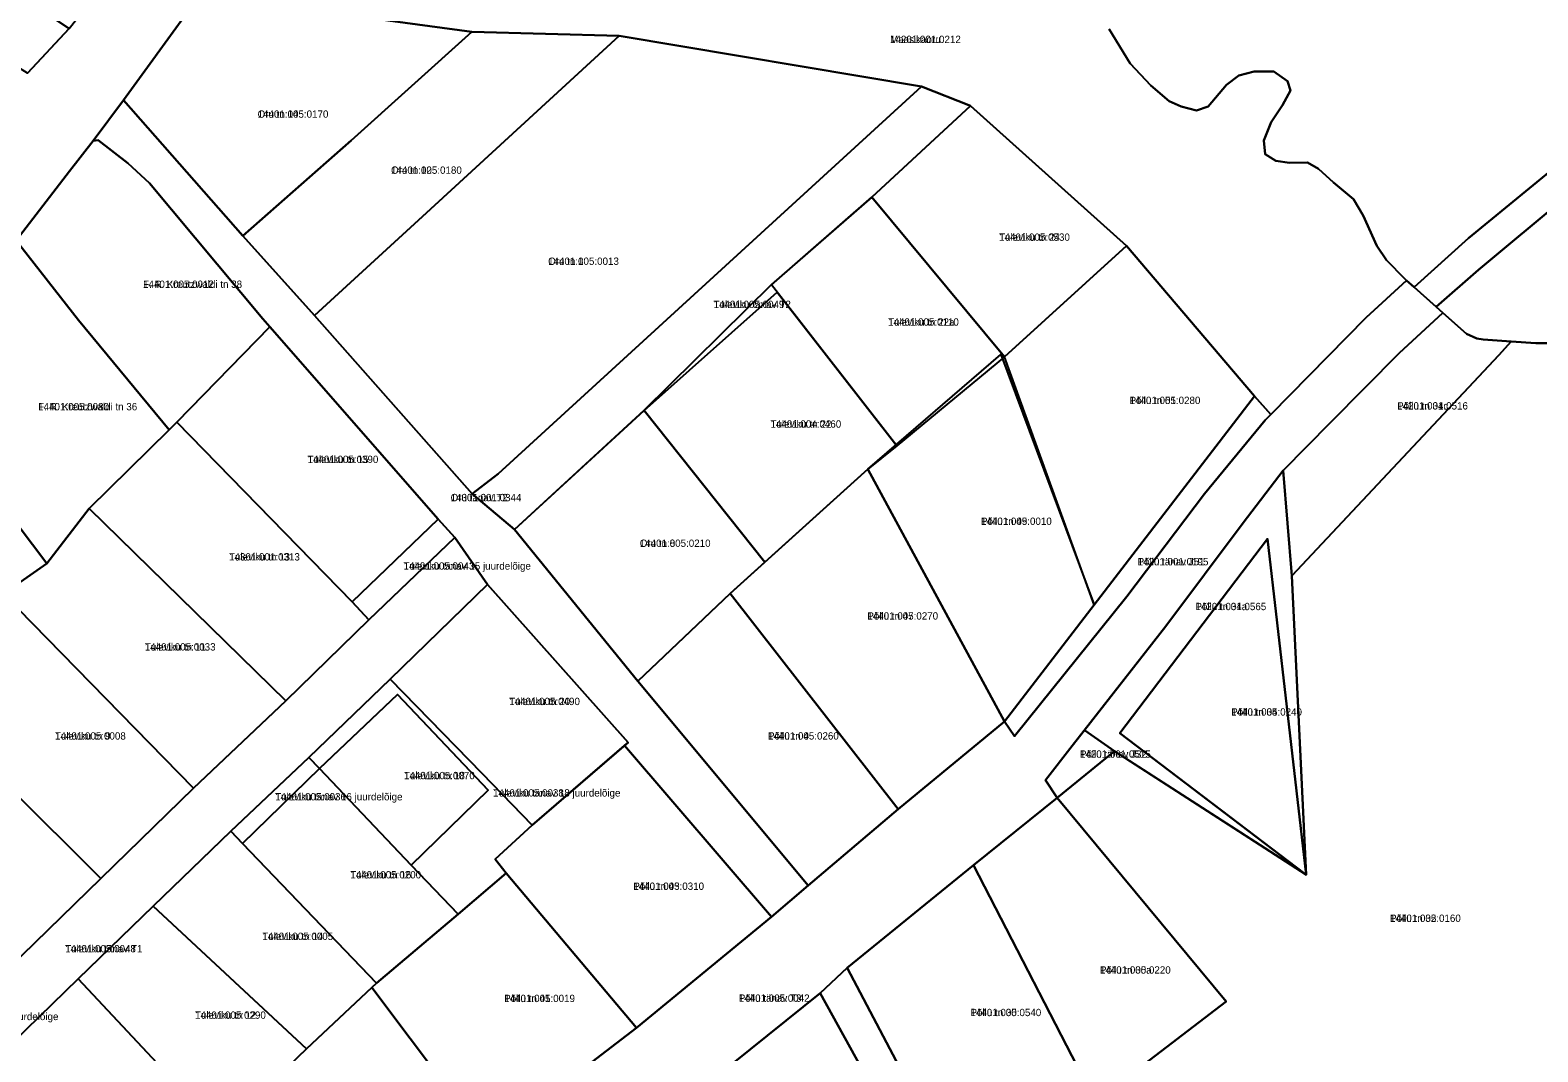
# Model space of a CAD drawing. Extents: x 640657 to 665127, y 6395726 to 6426831.
# Drawn here: x 650809.6 to 651118.5, y 6412851.6 to 6413060.8 of the extents above; entities that cross this region are included whole.
import ezdxf

# ---------------------------------------------------------------- set-up
doc = ezdxf.new("R2010")
doc.units = 0
for name, color, linetype in [('L_AADRESS', 7, 'Continuous'), ('PIIR', 7, 'Continuous'), ('TUNNUS', 7, 'Continuous')]:
    doc.layers.add(name, color=color, linetype=linetype)

msp = doc.modelspace()

# ---------------------------------------------------------------- linework, layer by layer
at = {"layer": 'PIIR'}
for points in [[(650639.81, 6413174.35), (650661.38, 6413159.66), (650687.87, 6413141.56), (650726.69, 6413115.56), (650728.32, 6413120.2), (650817.6, 6413061.15), (650809.09, 6413051.96), (650774.49, 6413073.67), (650757.49, 6413085.02), (650736.91, 6413098.43), (650728.56, 6413104.06), (650707.39, 6413117.67), (650694.6, 6413126.1), (650690.86, 6413128.47), (650674.2, 6413139.68), (650668.91, 6413143.29), (650635.45, 6413166.68)], [(650828.73, 6413046.43), (650842.18, 6413064.93), (650852, 6413067.01), (650900.11, 6413060.4), (650875.35, 6413038.19), (650853.19, 6413018.67)], [(650889.96, 6413022.62), (650867.85, 6413002.33), (650853.19, 6413018.67), (650875.35, 6413038.19), (650900.11, 6413060.4), (650930.28, 6413059.63)], [(650930.28, 6413059.63), (650992.19, 6413049.22), (650905.51, 6412969.94), (650900.17, 6412965.79), (650867.85, 6413002.33), (650889.96, 6413022.62)], [(650900.17, 6412965.79), (650905.51, 6412969.94), (650992.19, 6413049.22), (651002.25, 6413045.27), (650982.01, 6413026.6), (650961.49, 6413008.66), (650935.36, 6412982.86), (650908.86, 6412958.51)], [(650822.51, 6413038.14), (650828.73, 6413046.43), (650853.19, 6413018.67), (650867.85, 6413002.33), (650900.17, 6412965.79), (650908.86, 6412958.51), (650934.1, 6412927.48), (650968.99, 6412885.61), (650961.49, 6412879.2), (650931.36, 6412914.3), (650932.1, 6412914.93), (650903.31, 6412947.28), (650896.59, 6412956.91), (650893.22, 6412960.61), (650858.72, 6412999.99), (650857.25, 6413001.69), (650834.03, 6413029.42), (650829.61, 6413033.56), (650823.57, 6413038.25)], [(650982.01, 6413026.6), (651002.25, 6413045.27), (651034.21, 6413016.63), (651009.24, 6412993.91)], [(650806.76, 6413017.69), (650817.7, 6413031.91), (650822.51, 6413038.14), (650823.57, 6413038.25), (650829.61, 6413033.56), (650834.03, 6413029.42), (650857.25, 6413001.69), (650858.72, 6412999.99), (650839.66, 6412980.52), (650838.08, 6412978.9), (650819.54, 6413001.38)], [(650987.17, 6412975.63), (650961.49, 6413008.65), (650982.01, 6413026.6), (651009.24, 6412993.91)], [(650806.76, 6413017.69), (650819.54, 6413001.38), (650838.08, 6412978.9), (650821.71, 6412962.79), (650813.02, 6412951.56), (650784.43, 6412989.36)], [(651009.24, 6412993.91), (651034.21, 6413016.63), (651060.45, 6412985.8), (651027.56, 6412943.08)], [(650960.14, 6412951.85), (650935.37, 6412982.87), (650962.68, 6413007.13), (650987.17, 6412975.63), (650981.24, 6412970.86)], [(651099, 6413002.9), (651103.86, 6412998.61), (651105.99, 6412997.64), (651107.31, 6412997.44), (651113.02, 6412997.03), (651110.49, 6412994.23), (651068.11, 6412949.05), (651066.3, 6412970.6), (651076, 6412980.4), (651090.1, 6412994.6)], [(650875.6, 6412943.69), (650839.66, 6412980.52), (650858.72, 6412999.99), (650893.22, 6412960.61)], [(651027.56, 6412943.08), (651009.2, 6412919.23), (650981.24, 6412970.86), (651008.5, 6412994.35)], [(650760.68, 6412958.63), (650784.43, 6412989.36), (650813.02, 6412951.56), (650804.18, 6412945.36), (650788.46, 6412927.08)], [(651009.2, 6412919.23), (651027.56, 6412943.08), (651060.45, 6412985.8), (651063.77, 6412982.09), (651062.6, 6412980.9), (651050.2, 6412965.8), (651034.3, 6412944.8), (651011.3, 6412916.2)], [(650934.1, 6412927.48), (650908.86, 6412958.51), (650935.37, 6412982.87), (650960.14, 6412951.85), (650953.05, 6412945.43)], [(650862, 6412923.4), (650821.71, 6412962.79), (650838.08, 6412978.9), (650839.66, 6412980.52), (650875.6, 6412943.69), (650879, 6412940)], [(650981.24, 6412970.86), (651009.2, 6412919.23), (650987.44, 6412901.27), (650953.05, 6412945.43)], [(651071.04, 6412887.8), (651063.12, 6412956.6), (651032.82, 6412916.84), (651070.71, 6412888.05), (651031.76, 6412913.14), (651025.64, 6412917.44), (651042.3, 6412938.7), (651058.1, 6412959.9), (651066.3, 6412970.6), (651068.11, 6412949.05)], [(650843.09, 6412905.57), (650804.18, 6412945.36), (650813.02, 6412951.56), (650821.71, 6412962.79), (650862, 6412923.4)], [(650875.6, 6412943.69), (650893.22, 6412960.61), (650896.59, 6412956.91), (650879, 6412940)], [(650727.79, 6412797.05), (650764.12, 6412829.22), (650781.76, 6412846.39), (650802.47, 6412866.04), (650824.08, 6412887.05), (650843.09, 6412905.57), (650862, 6412923.4), (650879, 6412940), (650896.59, 6412956.91), (650903.31, 6412947.28), (650883.38, 6412927.9), (650866.67, 6412911.86), (650850.73, 6412896.72), (650834.83, 6412881.39), (650819.43, 6412866.53), (650803.47, 6412850.91), (650787.59, 6412835.68), (650771.66, 6412820.55), (650754.96, 6412806.32), (650734.58, 6412786.93)], [(651032.82, 6412916.84), (651063.12, 6412956.6), (651071.04, 6412887.8)], [(650786.31, 6412924.61), (650788.46, 6412927.08), (650804.18, 6412945.36), (650843.09, 6412905.57), (650824.08, 6412887.05)], [(650903.31, 6412947.28), (650932.1, 6412914.93), (650912.45, 6412897.98), (650902.19, 6412908.54), (650883.38, 6412927.9)], [(650934.1, 6412927.48), (650953.05, 6412945.43), (650987.44, 6412901.27), (650968.99, 6412885.61)], [(650866.67, 6412911.86), (650883.38, 6412927.9), (650902.19, 6412908.54), (650912.45, 6412897.98), (650904.84, 6412891.04), (650907.12, 6412888.13), (650897.27, 6412879.76), (650887.68, 6412889.81), (650903.47, 6412905.15), (650884.89, 6412924.75), (650868.91, 6412909.55)], [(650759.7, 6412894.12), (650786.31, 6412924.61), (650824.08, 6412887.05), (650802.47, 6412866.04), (650783.09, 6412886.6), (650780.41, 6412884.25), (650772.63, 6412877.46)], [(650868.91, 6412909.55), (650884.89, 6412924.75), (650903.47, 6412905.15), (650887.68, 6412889.81)], [(651017.6, 6412907.2), (651023.1, 6412914.2), (651025.64, 6412917.44), (651031.76, 6412913.14), (651020.04, 6412903.56)], [(650904.84, 6412891.04), (650912.45, 6412897.98), (650931.36, 6412914.3), (650961.49, 6412879.2), (650933.81, 6412856.48), (650907.12, 6412888.13)], [(650850.73, 6412896.72), (650866.67, 6412911.86), (650868.91, 6412909.55), (650853.13, 6412894.23)], [(650868.91, 6412909.55), (650887.68, 6412889.81), (650897.27, 6412879.76), (650880.55, 6412865.6), (650853.13, 6412894.23)], [(651020.04, 6412903.56), (651054.65, 6412861.84), (651027.83, 6412841.38), (651027.51, 6412842), (651002.89, 6412889.77)], [(650834.83, 6412881.39), (650850.73, 6412896.72), (650853.13, 6412894.23), (650880.55, 6412865.6), (650879.63, 6412864.72), (650866.25, 6412852.19)], [(650977, 6412868.75), (651002.89, 6412889.77), (651027.51, 6412842), (650999.1, 6412826.78)], [(650903.37, 6412833.12), (650879.63, 6412864.72), (650880.55, 6412865.6), (650897.27, 6412879.76), (650907.12, 6412888.13), (650933.81, 6412856.48)], [(650848.73, 6412835.25), (650819.43, 6412866.53), (650834.83, 6412881.39), (650866.25, 6412852.19), (650851.7, 6412838.15)], [(650971.47, 6412863.56), (650977, 6412868.75), (650999.1, 6412826.78), (651019.7, 6412787.3), (651032.19, 6412764.47), (651050.32, 6412732.33), (651067.41, 6412700.48), (651056.04, 6412699.1), (651029.47, 6412750.52), (651012.39, 6412782.96), (651008.19, 6412791.21), (650992.2, 6412821.17), (650988.87, 6412827.17), (650990.98, 6412828.18)], [(650803.47, 6412850.91), (650819.43, 6412866.53), (650848.73, 6412835.25), (650831.89, 6412821.36)], [(650873.56, 6412808.84), (650851.7, 6412838.15), (650866.25, 6412852.19), (650879.63, 6412864.72), (650903.37, 6412833.12)], [(650971.47, 6412863.56), (650990.98, 6412828.18), (650988.87, 6412827.17), (650992.2, 6412821.17), (650954.39, 6412801.05), (650935.96, 6412835.02)]]:
    msp.add_lwpolyline(points, close=True, dxfattribs=at)
for points in [[(650809.09, 6413051.96), (650817.6, 6413061.15), (650824.33, 6413069.75), (650879.77, 6413140.76), (650884.47, 6413146.87), (650897.48, 6413138.36), (650900.25, 6413136.22), (650842.18, 6413064.93), (650828.73, 6413046.43), (650822.51, 6413038.14), (650817.7, 6413031.91), (650806.76, 6413017.69)], [(651030.69, 6413060.95), (651034.94, 6413053.96), (651039.23, 6413049.46), (651042.97, 6413046.24), (651045.44, 6413045.13), (651048.54, 6413044.3), (651050.93, 6413045.11), (651054.69, 6413049.58), (651057.26, 6413051.5), (651060.38, 6413052.31), (651064.41, 6413052.29), (651067.23, 6413050.36), (651067.78, 6413048.44), (651066.2, 6413045.41), (651063.82, 6413041.95), (651062.34, 6413038.21), (651062.6, 6413035.37), (651064.8, 6413033.99), (651067.63, 6413033.61), (651071.29, 6413033.69), (651073.58, 6413032.4), (651076.59, 6413029.55), (651080.69, 6413026.15), (651082.69, 6413022.85), (651085.51, 6413016.62), (651087.51, 6413013.68), (651091.21, 6413009.87), (651091.6, 6413009.5), (651083.3, 6413001.9), (651063.77, 6412982.09), (651060.45, 6412985.8), (651034.21, 6413016.63), (651002.25, 6413045.27), (650992.19, 6413049.22), (650930.28, 6413059.63), (650900.11, 6413060.4), (650852, 6413067.01)], [(651120.93, 6413031.84), (651104.31, 6413018.18), (651093.14, 6413008.14), (651091.6, 6413009.5), (651091.21, 6413009.87), (651087.51, 6413013.68), (651085.51, 6413016.62), (651082.69, 6413022.85), (651080.69, 6413026.15), (651076.59, 6413029.55), (651073.58, 6413032.4), (651071.29, 6413033.69), (651067.63, 6413033.61), (651064.8, 6413033.99), (651062.6, 6413035.37), (651062.34, 6413038.21), (651063.82, 6413041.95), (651066.2, 6413045.41), (651067.78, 6413048.44), (651067.23, 6413050.36), (651064.41, 6413052.29), (651060.38, 6413052.31), (651057.26, 6413051.5), (651054.69, 6413049.58), (651050.93, 6413045.11), (651048.54, 6413044.3), (651045.44, 6413045.13), (651042.97, 6413046.24), (651039.23, 6413049.46), (651034.94, 6413053.96), (651030.69, 6413060.95)], [(651124.3, 6413026.65), (651106.32, 6413011.7), (651097.65, 6413004.1), (651093.14, 6413008.14), (651104.31, 6413018.18), (651120.93, 6413031.84)], [(651121.96, 6412996.66), (651118.1, 6412996.68), (651113.02, 6412997.03), (651107.31, 6412997.44), (651105.99, 6412997.64), (651103.86, 6412998.61), (651099, 6413002.9), (651097.65, 6413004.1), (651106.32, 6413011.7), (651124.3, 6413026.65)], [(650903.37, 6412833.12), (650933.81, 6412856.48), (650961.49, 6412879.2), (650968.99, 6412885.61), (650987.44, 6412901.27), (651009.2, 6412919.23), (651011.3, 6412916.2), (651034.3, 6412944.8), (651050.2, 6412965.8), (651062.6, 6412980.9), (651063.77, 6412982.09), (651083.3, 6413001.9), (651091.6, 6413009.5), (651093.14, 6413008.14), (651097.65, 6413004.1), (651099, 6413002.9), (651090.1, 6412994.6), (651076, 6412980.4), (651066.3, 6412970.6), (651058.1, 6412959.9), (651042.3, 6412938.7), (651023.1, 6412914.2), (651017.6, 6412907.2), (651020.04, 6412903.56), (651002.89, 6412889.77), (650977, 6412868.75), (650971.47, 6412863.56), (650935.96, 6412835.02)], [(651125.47, 6412804.8), (651098.44, 6412791.06), (651063.81, 6412773.45), (651062.46, 6412776.05), (651059.6, 6412781.58), (651054.92, 6412790.21), (651047.54, 6412803.77), (651027.83, 6412841.38), (651054.65, 6412861.84), (651020.04, 6412903.56), (651031.76, 6412913.14), (651071.04, 6412887.8), (651068.11, 6412949.05), (651110.49, 6412994.23), (651113.02, 6412997.03), (651118.1, 6412996.68), (651121.96, 6412996.66)]]:
    msp.add_lwpolyline(points, dxfattribs=at)

# ---------------------------------------------------------------- texts
at = {"layer": 'L_AADRESS'}
for s, p in [('Maasikaoru', (650985.77, 6413058.14)), ('Oru tn 14', (650856.21, 6413042.84)), ('Oru tn 12', (650883.54, 6413031.36)), ('Tuleviku tn 24', (651008.11, 6413017.64)), ('Oru tn 10', (650915.72, 6413012.71)), ('F. R. Kreutzwaldi tn 38', (650832.74, 6413008)), ('Tuleviku tänav T2', (650949.62, 6413003.87)), ('Tuleviku tn 22a', (650985.37, 6413000.26)), ('Põllu tn 51', (651034.85, 6412984.21)), ('F. R. Kreutzwaldi tn 36', (650811.25, 6412982.92)), ('Põllu tn 34c', (651089.66, 6412983.09)), ('Tuleviku tn 22', (650961.27, 6412979.37)), ('Tuleviku tn 15', (650866.44, 6412972.13)), ('Oru tänav T2', (650895.75, 6412964.31)), ('Põllu tn 49', (651004.4, 6412959.46)), ('Oru tn 8', (650934.5, 6412954.96)), ('Tuleviku tn 13', (650850.36, 6412952.17)), ('Tuleviku tänav 15 juurdelõige', (650886.1, 6412950.3)), ('Põllu tänav J51', (651036.49, 6412951.18)), ('Põllu tn 34a', (651048.34, 6412942)), ('Põllu tn 47', (650981.12, 6412940.07)), ('Tuleviku tn 11', (650833.09, 6412933.73)), ('Tuleviku tn 20', (650907.74, 6412922.56)), ('Põllu tn 34', (651055.66, 6412920.41)), ('Tuleviku tn 9', (650814.7, 6412915.49)), ('Põllu tn 45', (650960.77, 6412915.5)), ('Põllu tänav J32', (651024.68, 6412911.78)), ('Tuleviku tn 18', (650886.19, 6412907.38)), ('Tuleviku tänav 18 juurdelõige', (650904.44, 6412903.83)), ('Tuleviku tänav 16 juurdelõige', (650859.8, 6412903.04)), ('Tuleviku tn 16', (650875.2, 6412887.06)), ('Põllu tn 43', (650933.17, 6412884.72)), ('Põllu tn 32', (651088.2, 6412878.16)), ('Tuleviku tn 14', (650857.18, 6412874.46)), ('Tuleviku tänav T1', (650816.77, 6412871.92)), ('Põllu tn 30a', (651028.77, 6412867.57)), ('Põllu tn 41', (650906.72, 6412861.74)), ('Põllu tänav T3', (650954.79, 6412861.8)), ('Tuleviku tänav 5 juurdelõige', (650790.43, 6412858.04)), ('Tuleviku tn 12', (650843.39, 6412858.32)), ('Põllu tn 30', (651002.25, 6412858.86))]:
    msp.add_text(s, height=1.5, dxfattribs=at).set_placement(p)
at = {"layer": 'TUNNUS'}
for s, p in [('14201:001:0212', (650985.77, 6413058.14)), ('14401:005:0170', (650856.21, 6413042.84)), ('14401:005:0180', (650883.54, 6413031.36)), ('14401:005:0530', (651008.11, 6413017.64)), ('14401:005:0013', (650915.72, 6413012.71)), ('14401:005:0012', (650832.74, 6413008)), ('14401:005:0049', (650949.62, 6413003.87)), ('14401:005:0110', (650985.37, 6413000.26)), ('14401:005:0280', (651034.85, 6412984.21)), ('14401:005:0080', (650811.25, 6412982.92)), ('14201:001:0516', (651089.66, 6412983.09)), ('14401:004:0460', (650961.27, 6412979.37)), ('14401:005:0390', (650866.44, 6412972.13)), ('14301:001:0344', (650895.75, 6412964.31)), ('14401:005:0010', (651004.4, 6412959.46)), ('14401:005:0210', (650934.5, 6412954.96)), ('14301:001:0313', (650850.36, 6412952.17)), ('14401:005:0043', (650886.1, 6412950.3)), ('14201:001:0195', (651036.49, 6412951.18)), ('14201:001:0565', (651048.34, 6412942)), ('14401:005:0270', (650981.12, 6412940.07)), ('14401:005:0033', (650833.09, 6412933.73)), ('14401:005:0490', (650907.74, 6412922.56)), ('14401:005:0240', (651055.66, 6412920.41)), ('14401:005:0008', (650814.7, 6412915.49)), ('14401:005:0260', (650960.77, 6412915.5)), ('14201:001:0515', (651024.68, 6412911.78)), ('14401:005:0070', (650886.19, 6412907.38)), ('14401:005:0038', (650904.44, 6412903.83)), ('14401:005:0036', (650859.8, 6412903.04)), ('14401:005:0200', (650875.2, 6412887.06)), ('14401:005:0310', (650933.17, 6412884.72)), ('14401:005:0160', (651088.2, 6412878.16)), ('14401:005:0005', (650857.18, 6412874.46)), ('14401:005:0048', (650816.77, 6412871.92)), ('14401:005:0220', (651028.77, 6412867.57)), ('14401:005:0019', (650906.72, 6412861.74)), ('14401:005:0042', (650954.79, 6412861.8)), ('14401:005:0290', (650843.39, 6412858.32)), ('14401:005:0540', (651002.25, 6412858.86))]:
    msp.add_text(s, height=1.5, dxfattribs=at).set_placement(p)

doc.saveas('drawing.dxf')
